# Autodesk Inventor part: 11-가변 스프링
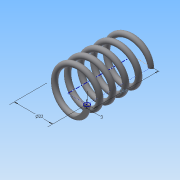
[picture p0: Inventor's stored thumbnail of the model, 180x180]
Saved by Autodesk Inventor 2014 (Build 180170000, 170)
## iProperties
Created: 2015-09
Part Number: 11-가변 스프링
Material: 강철, 탄소
Document SubType Name: Modeling
Designer: study
Density: 7.87 g/cm^3
Appearance: 반연마
Mass: 18.8856 g
Surface Area: 32.5491 cm^2
Volume: 2.3997 cm^3
Author: study
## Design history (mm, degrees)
sketch "스케치1"
  geometry: L1 (0, 0)-(11, 0); L2 (11, 0)-(11, 36.411); L3 (11, 36.411)-(0, 36.411); L4 (0, 36.411)-(0, 0); C1 r 1.5 at (11, 0)
  constraints: 8 end point, 2 parallel, 1 centre point, 1 coincident, 1 horizontal, 1 perpendicular
  dimensions: "d0" = 22 diameter of L2 L4; "d1" = 36.4112 distance of L1.end L2.end (derived); "d2" = 3 diameter of C1
feature "코일1" sketch "스케치1" pitch "d3" = 10; turns "d5" = 5; dims "d4" = 36.4112 (= d1), "d6" = 0, angle "d7" = 90 deg, angle "d8" = 90 deg, "d9" = 0, "d10" = 0
node "작업 평면1"
sketch "스케치2"
  geometry: L1 (-12.5, 0)-(-9.5, 0) reference; 1 further point
  constraints: 1 horizontal alignment
extrude "돌출1" cut sketch "스케치2" stored distance "d12" = 10; taper "d13" = 0 deg
node "작업 평면2"
sketch "스케치3"
  geometry: L1 (-9.5, 0)-(-12.5, 0) reference; 1 further point
  constraints: 1 horizontal alignment
extrude "돌출2" cut sketch "스케치3" stored distance "d15" = 10; taper "d16" = 0 deg
node "솔리드1"
node "절단 모서리 투영1"
node "절단 모서리 투영2"
other parameters: "d11" = 0, "d14" = 36.4112 (= d1)
